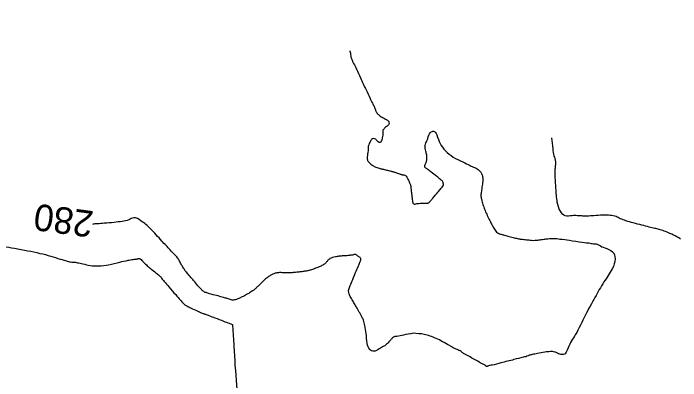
# Model space of a CAD drawing. Extents: x -478102 to -473059, y -1117705 to -1114104.
# Drawn here: x -474560.9 to -474460.1, y -1114300.7 to -1114245.3 of the extents above; entities that cross this region are included whole.
import ezdxf

# ---------------------------------------------------------------- set-up
doc = ezdxf.new("R2010")
doc.units = 0
for name, color, linetype in [('Vrstevnice_hlavni', 7, 'Continuous'), ('Vrstevnice_popis', 7, 'Continuous'), ('Vrstevnice_vedlejsi', 7, 'Continuous')]:
    doc.layers.add(name, color=color, linetype=linetype)

msp = doc.modelspace()

# ---------------------------------------------------------------- linework, layer by layer
at = {"layer": 'Vrstevnice_hlavni'}
for points in [[(-474510.104, -1114250.97), (-474510.091, -1114251.018), (-474510.014, -1114251.351), (-474509.96, -1114251.74), (-474509.859, -1114252.123), (-474509.71, -1114252.502), (-474509.513, -1114252.875), (-474509.103, -1114253.728), (-474508.479, -1114255.061), (-474507.64, -1114256.874), (-474507.041, -1114258.153), (-474506.68, -1114258.898), (-474506.557, -1114259.11), (-474506.422, -1114259.396), (-474506.273, -1114259.758)], [(-474506.273, -1114259.758), (-474506.111, -1114260.194), (-474505.763, -1114260.61), (-474505.229, -1114261.006), (-474504.508, -1114261.383), (-474504.179, -1114261.757), (-474504.243, -1114262.13), (-474504.7, -1114262.502), (-474504.996, -1114262.829), (-474505.131, -1114263.113), (-474505.106, -1114263.352), (-474505.131, -1114263.683), (-474505.208, -1114264.104), (-474505.337, -1114264.617), (-474505.543, -1114264.826), (-474505.826, -1114264.731), (-474506.188, -1114264.332), (-474506.515, -1114264.212), (-474506.807, -1114264.37), (-474507.065, -1114264.806), (-474507.234, -1114265.156), (-474507.313, -1114265.419), (-474507.303, -1114265.596), (-474507.322, -1114265.879), (-474507.37, -1114266.27), (-474507.447, -1114266.768), (-474507.472, -1114267.153), (-474507.445, -1114267.423), (-474507.367, -1114267.579), (-474507.232, -1114267.756), (-474507.04, -1114267.954), (-474506.791, -1114268.173), (-474506.538, -1114268.351), (-474506.281, -1114268.489), (-474506.019, -1114268.587), (-474505.642, -1114268.698), (-474505.148, -1114268.823), (-474504.538, -1114268.961), (-474503.987, -1114269.1), (-474503.496, -1114269.24), (-474503.063, -1114269.38), (-474502.726, -1114269.492), (-474502.482, -1114269.576), (-474502.333, -1114269.633), (-474502.17, -1114269.676), (-474501.991, -1114269.705), (-474501.797, -1114269.721), (-474501.592, -1114269.896), (-474501.375, -1114270.23), (-474501.147, -1114270.724), (-474500.992, -1114271.081), (-474500.91, -1114271.302), (-474500.9, -1114271.385), (-474500.867, -1114271.678), (-474500.811, -1114272.179), (-474500.732, -1114272.888), (-474500.665, -1114273.421), (-474500.611, -1114273.778), (-474500.569, -1114273.96), (-474500.449, -1114274.063), (-474500.25, -1114274.087), (-474499.973, -1114274.034), (-474499.649, -1114273.997), (-474499.277, -1114273.975), (-474498.859, -1114273.97), (-474498.548, -1114273.961), (-474498.344, -1114273.946), (-474498.248, -1114273.927), (-474498.127, -1114273.846), (-474497.98, -1114273.702), (-474497.808, -1114273.495), (-474497.51, -1114273.141), (-474497.084, -1114272.641), (-474496.532, -1114271.992), (-474496.161, -1114271.531), (-474495.97, -1114271.258), (-474495.959, -1114271.171), (-474495.97, -1114271.056), (-474496.002, -1114270.912), (-474496.054, -1114270.74), (-474496.379, -1114270.407), (-474496.976, -1114269.914), (-474497.844, -1114269.26), (-474498.433, -1114268.799), (-474498.743, -1114268.53), (-474498.773, -1114268.455), (-474498.745, -1114268.284), (-474498.658, -1114268.017), (-474498.512, -1114267.656), (-474498.456, -1114267.219), (-474498.49, -1114266.708), (-474498.615, -1114266.122), (-474498.698, -1114265.686), (-474498.74, -1114265.399), (-474498.741, -1114265.263), (-474498.601, -1114264.866), (-474498.32, -1114264.208)], [(-474498.32, -1114264.208), (-474497.898, -1114263.29), (-474497.45, -1114263.108), (-474496.974, -1114263.664), (-474496.471, -1114264.956), (-474495.643, -1114266.068), (-474494.49, -1114266.999), (-474493.012, -1114267.75), (-474491.938, -1114268.282), (-474491.268, -1114268.595), (-474491.003, -1114268.69), (-474490.736, -1114268.866), (-474490.468, -1114269.125), (-474490.199, -1114269.466), (-474490.054, -1114269.978), (-474490.035, -1114270.659), (-474490.141, -1114271.511), (-474490.224, -1114272.138), (-474490.283, -1114272.54), (-474490.318, -1114272.716), (-474490.272, -1114273.074), (-474490.145, -1114273.612), (-474489.937, -1114274.33), (-474489.669, -1114275.067), (-474489.341, -1114275.822), (-474488.953, -1114276.596), (-474488.629, -1114277.225), (-474488.369, -1114277.71), (-474488.171, -1114278.051), (-474487.936, -1114278.316), (-474487.664, -1114278.505), (-474487.355, -1114278.617), (-474486.879, -1114278.762), (-474486.236, -1114278.939), (-474485.427, -1114279.148), (-474484.756, -1114279.299), (-474484.222, -1114279.393), (-474483.825, -1114279.429), (-474483.433, -1114279.47), (-474483.048, -1114279.515), (-474482.668, -1114279.566), (-474482.171, -1114279.564), (-474481.556, -1114279.509), (-474480.824, -1114279.402), (-474480.202, -1114279.327), (-474479.69, -1114279.286), (-474479.289, -1114279.279), (-474478.373, -1114279.368), (-474476.943, -1114279.555), (-474474.999, -1114279.839), (-474473.676, -1114280.026), (-474472.974, -1114280.117), (-474472.894, -1114280.112), (-474472.442, -1114280.304), (-474471.618, -1114280.694), (-474470.422, -1114281.281), (-474470.043, -1114282.336), (-474470.481, -1114283.859), (-474471.737, -1114285.851), (-474473.084, -1114288.173), (-474474.521, -1114290.825), (-474476.049, -1114293.806), (-474477.152, -1114295.796), (-474477.829, -1114296.793), (-474478.08, -1114296.798), (-474478.387, -1114296.737), (-474478.749, -1114296.609), (-474479.166, -1114296.415), (-474479.808, -1114296.354), (-474480.673, -1114296.425), (-474481.762, -1114296.63), (-474482.541, -1114296.791), (-474483.009, -1114296.91), (-474483.167, -1114296.987), (-474483.934, -1114297.202), (-474485.309, -1114297.556), (-474487.293, -1114298.05), (-474488.628, -1114298.385), (-474489.313, -1114298.563), (-474489.347, -1114298.584), (-474489.387, -1114298.593), (-474489.431, -1114298.59), (-474489.479, -1114298.576), (-474489.521, -1114298.556), (-474489.556, -1114298.53), (-474489.585, -1114298.498), (-474489.993, -1114298.258), (-474490.78, -1114297.812), (-474491.946, -1114297.158), (-474492.73, -1114296.716), (-474493.13, -1114296.485), (-474493.147, -1114296.466), (-474493.81, -1114296.106), (-474495.121, -1114295.403), (-474497.078, -1114294.359), (-474498.879, -1114293.755), (-474500.524, -1114293.592)], [(-474536.346, -1114281.886), (-474536.522, -1114281.747), (-474537.225, -1114281.017), (-474538.455, -1114279.698), (-474540.213, -1114277.789), (-474541.632, -1114276.615), (-474542.713, -1114276.176), (-474543.454, -1114276.472), (-474544.442, -1114276.706), (-474545.676, -1114276.879), (-474547.155, -1114276.99), (-474548.174, -1114277.072), (-474548.732, -1114277.124), (-474548.929, -1114277.17)], [(-474500.524, -1114293.592), (-474502.013, -1114293.868), (-474503.01, -1114294.055), (-474503.516, -1114294.153), (-474503.529, -1114294.162), (-474503.682, -1114294.326), (-474503.975, -1114294.644), (-474504.406, -1114295.117), (-474504.967, -1114295.552), (-474505.657, -1114295.949), (-474506.475, -1114296.307), (-474507.077, -1114296.035), (-474507.463, -1114295.132), (-474507.633, -1114293.597), (-474507.823, -1114292.418), (-474508.034, -1114291.594), (-474508.265, -1114291.126), (-474508.493, -1114290.687), (-474508.716, -1114290.276), (-474508.935, -1114289.893), (-474509.213, -1114289.417), (-474509.551, -1114288.848), (-474509.949, -1114288.187), (-474510.196, -1114287.657), (-474510.291, -1114287.259), (-474510.235, -1114286.993), (-474510.024, -1114286.396), (-474509.656, -1114285.469), (-474509.133, -1114284.211), (-474508.753, -1114283.305), (-474508.518, -1114282.751), (-474508.427, -1114282.548), (-474508.415, -1114282.375), (-474508.484, -1114282.232), (-474508.632, -1114282.119), (-474508.79, -1114282.002), (-474508.958, -1114281.881), (-474509.136, -1114281.756), (-474509.289, -1114281.694), (-474509.418, -1114281.694), (-474509.522, -1114281.758), (-474509.837, -1114281.816), (-474510.362, -1114281.868), (-474511.097, -1114281.914), (-474511.734, -1114281.978), (-474512.273, -1114282.059), (-474512.714, -1114282.158), (-474513.091, -1114282.331), (-474513.404, -1114282.579), (-474513.653, -1114282.901), (-474514.044, -1114283.211), (-474514.577, -1114283.507), (-474515.252, -1114283.789), (-474515.867, -1114284.006), (-474516.421, -1114284.157), (-474516.915, -1114284.242), (-474517.475, -1114284.319), (-474518.102, -1114284.388), (-474518.795, -1114284.448), (-474519.441, -1114284.476), (-474520.041, -1114284.471), (-474520.593, -1114284.434), (-474521.106, -1114284.48), (-474521.579, -1114284.61), (-474522.013, -1114284.824), (-474522.458, -1114285.117), (-474522.914, -1114285.488), (-474523.382, -1114285.938), (-474523.8, -1114286.336), (-474524.169, -1114286.682), (-474524.487, -1114286.976), (-474524.931, -1114287.298), (-474525.498, -1114287.646), (-474526.191, -1114288.021), (-474526.758, -1114288.298), (-474527.199, -1114288.476), (-474527.514, -1114288.555), (-474527.829, -1114288.568), (-474528.142, -1114288.513), (-474528.455, -1114288.392), (-474528.987, -1114288.228), (-474529.739, -1114288.019), (-474530.711, -1114287.766), (-474531.433, -1114287.563), (-474531.907, -1114287.41), (-474532.131, -1114287.308), (-474532.501, -1114286.979), (-474533.016, -1114286.424), (-474533.677, -1114285.643), (-474534.2, -1114285.027), (-474534.587, -1114284.578), (-474534.837, -1114284.294), (-474535.124, -1114283.884), (-474535.448, -1114283.348), (-474535.809, -1114282.687), (-474536.109, -1114282.199), (-474536.346, -1114281.886)]]:
    msp.add_spline(points, degree=3, dxfattribs=at)
at = {"layer": 'Vrstevnice_vedlejsi'}
for points in [[(-474552.854, -1114311.249), (-474553.079, -1114311.087), (-474553.821, -1114310.574), (-474555.08, -1114309.711), (-474556.857, -1114308.497), (-474559.696, -1114307.123), (-474563.598, -1114305.587), (-474568.562, -1114303.891), (-474573.331, -1114301.997), (-474577.905, -1114299.906), (-474582.284, -1114297.617), (-474585.674, -1114295.919), (-474588.077, -1114294.812), (-474589.491, -1114294.296), (-474591.989, -1114293.662), (-474595.57, -1114292.908), (-474600.235, -1114292.036), (-474603.58, -1114291.444), (-474605.605, -1114291.133), (-474606.31, -1114291.102), (-474606.928, -1114291.027), (-474607.46, -1114290.909), (-474607.905, -1114290.747), (-474608.453, -1114290.591), (-474609.102, -1114290.44), (-474609.854, -1114290.294), (-474613.621, -1114289.328), (-474620.404, -1114287.542), (-474630.202, -1114284.937), (-474637.239, -1114282.941), (-474641.515, -1114281.554), (-474643.03, -1114280.777), (-474646.226, -1114278.86), (-474651.102, -1114275.804), (-474657.658, -1114271.609), (-474662.169, -1114268.281), (-474664.633, -1114265.821), (-474665.051, -1114264.228), (-474666.944, -1114260.949), (-474670.313, -1114255.984), (-474675.156, -1114249.332), (-474681.278, -1114245.965), (-474688.679, -1114245.885), (-474697.358, -1114249.09), (-474704.556, -1114251.174), (-474710.273, -1114252.136), (-474714.508, -1114251.976), (-474720.156, -1114252.317), (-474727.217, -1114253.156), (-474735.691, -1114254.496), (-474743.099, -1114255.448), (-474749.443, -1114256.012), (-474754.721, -1114256.188), (-474759.428, -1114257.754), (-474763.562, -1114260.711), (-474767.123, -1114265.059), (-474771.341, -1114269.134), (-474776.214, -1114272.938), (-474781.743, -1114276.469), (-474786.123, -1114279.544), (-474789.352, -1114282.163), (-474791.432, -1114284.326), (-474793.539, -1114286.068), (-474795.674, -1114287.39), (-474797.837, -1114288.291), (-474801.021, -1114290.603), (-474805.227, -1114294.326), (-474810.453, -1114299.461), (-474815.93, -1114304.595), (-474821.656, -1114309.73), (-474827.632, -1114314.865), (-474832.327, -1114319.021), (-474835.739, -1114322.197), (-474837.87, -1114324.394), (-474841.8, -1114328.201), (-474847.532, -1114333.618), (-474855.063, -1114340.645), (-474860.556, -1114345.784), (-474864.01, -1114349.037), (-474865.424, -1114350.402), (-474866.85, -1114351.834), (-474868.286, -1114353.332), (-474869.734, -1114354.897), (-474871.228, -1114357.206), (-474872.768, -1114360.258), (-474874.355, -1114364.053), (-474875.677, -1114367.182), (-474876.734, -1114369.645), (-474877.527, -1114371.441), (-474878.751, -1114373.179), (-474880.405, -1114374.858), (-474882.489, -1114376.478), (-474884.757, -1114377.858), (-474887.208, -1114379), (-474889.844, -1114379.903), (-474893.032, -1114381.02), (-474896.771, -1114382.352)], [(-474620.341, -1114261.799), (-474618.559, -1114262.645), (-474617.158, -1114263.319), (-474616.138, -1114263.821), (-474615.498, -1114264.15), (-474614.425, -1114264.619), (-474612.918, -1114265.229), (-474610.977, -1114265.98), (-474609.537, -1114266.741), (-474608.6, -1114267.514), (-474608.165, -1114268.297), (-474607.008, -1114269.493), (-474605.13, -1114271.101), (-474602.53, -1114273.123), (-474600.61, -1114274.596), (-474599.369, -1114275.522), (-474598.808, -1114275.899), (-474598.164, -1114276.165), (-474597.435, -1114276.321), (-474596.623, -1114276.365), (-474595.719, -1114276.405), (-474594.722, -1114276.441), (-474593.634, -1114276.474), (-474592.211, -1114276.487), (-474590.452, -1114276.482), (-474588.358, -1114276.458), (-474586.824, -1114276.467), (-474585.851, -1114276.509), (-474585.439, -1114276.584), (-474584.626, -1114276.512), (-474583.414, -1114276.294), (-474581.803, -1114275.929), (-474580.635, -1114275.65), (-474579.911, -1114275.458), (-474579.631, -1114275.351), (-474579.116, -1114275.345), (-474578.366, -1114275.438), (-474577.382, -1114275.631), (-474576.639, -1114275.783), (-474576.138, -1114275.892), (-474575.878, -1114275.958), (-474575.186, -1114276.211), (-474574.064, -1114276.649), (-474572.511, -1114277.273), (-474570.896, -1114277.903), (-474569.219, -1114278.538), (-474567.479, -1114279.179), (-474565.99, -1114279.669), (-474564.75, -1114280.007), (-474563.76, -1114280.194), (-474562.421, -1114280.444), (-474560.735, -1114280.756), (-474558.7, -1114281.13), (-474556.865, -1114281.529), (-474555.23, -1114281.953), (-474553.795, -1114282.401), (-474552.741, -1114282.7), (-474552.068, -1114282.85), (-474551.775, -1114282.85), (-474551.216, -1114282.937), (-474550.39, -1114283.112), (-474549.296, -1114283.374), (-474548, -1114283.417), (-474546.501, -1114283.243), (-474544.799, -1114282.851), (-474543.57, -1114282.583), (-474542.814, -1114282.438), (-474542.531, -1114282.416), (-474542.295, -1114282.383), (-474542.106, -1114282.339), (-474541.964, -1114282.282), (-474541.757, -1114282.366), (-474541.486, -1114282.59), (-474541.15, -1114282.956), (-474540.684, -1114283.391), (-474540.089, -1114283.896), (-474539.364, -1114284.471), (-474538.858, -1114284.895), (-474538.572, -1114285.168), (-474538.506, -1114285.289), (-474538.118, -1114285.761), (-474537.408, -1114286.583), (-474536.377, -1114287.756), (-474535.649, -1114288.586), (-474535.225, -1114289.072), (-474535.103, -1114289.216), (-474534.714, -1114289.453), (-474534.056, -1114289.783), (-474533.129, -1114290.207), (-474532.46, -1114290.503), (-474532.048, -1114290.671), (-474531.893, -1114290.711), (-474531.359, -1114290.905), (-474530.447, -1114291.251), (-474529.157, -1114291.751), (-474528.294, -1114292.084), (-474527.857, -1114292.249)], [(-474460.148, -1114279.397), (-474460.742, -1114279.036), (-474461.76, -1114278.543), (-474462.649, -1114278.167), (-474463.41, -1114277.908), (-474464.042, -1114277.764), (-474464.903, -1114277.556), (-474465.993, -1114277.284), (-474467.312, -1114276.947), (-474468.401, -1114276.62), (-474469.26, -1114276.301), (-474469.89, -1114275.993), (-474470.768, -1114275.817), (-474471.894, -1114275.774), (-474473.268, -1114275.865), (-474474.282, -1114275.911), (-474474.936, -1114275.913), (-474475.23, -1114275.87), (-474475.765, -1114275.848), (-474476.541, -1114275.847), (-474477.559, -1114275.866), (-474478.303, -1114275.185), (-474478.774, -1114273.804), (-474478.97, -1114271.723), (-474479.077, -1114270.108), (-474479.092, -1114268.962), (-474479.017, -1114268.283), (-474479.014, -1114267.705), (-474479.083, -1114267.23), (-474479.224, -1114266.856), (-474479.406, -1114265.75), (-474479.607, -1114264.11)], [(-474553.927, -1114400.416), (-474553.474, -1114399.617), (-474552.966, -1114398.863), (-474552.405, -1114398.155), (-474551.791, -1114397.492), (-474551.19, -1114396.826), (-474550.604, -1114396.156), (-474550.032, -1114395.484), (-474549.553, -1114394.754), (-474549.166, -1114393.968), (-474548.873, -1114393.124), (-474548.652, -1114392.233), (-474548.504, -1114391.292), (-474548.43, -1114390.304), (-474548.405, -1114389.279), (-474548.431, -1114388.218), (-474548.507, -1114387.121), (-474548.593, -1114386.176), (-474548.689, -1114385.383), (-474548.794, -1114384.743), (-474548.782, -1114383.719), (-474548.652, -1114382.312), (-474548.405, -1114380.522), (-474548.2, -1114379.213), (-474548.037, -1114378.385), (-474547.916, -1114378.037), (-474547.76, -1114377.133), (-474547.57, -1114375.673), (-474547.346, -1114373.655), (-474547.183, -1114372.254), (-474547.08, -1114371.47), (-474547.037, -1114371.302), (-474546.918, -1114370.892), (-474546.722, -1114370.241), (-474546.45, -1114369.347), (-474546.291, -1114368.58), (-474546.246, -1114367.94), (-474546.315, -1114367.427), (-474546.69, -1114366.615), (-474547.372, -1114365.504), (-474548.361, -1114364.094), (-474549.165, -1114362.891), (-474549.784, -1114361.892), (-474550.219, -1114361.1), (-474550.631, -1114360.14), (-474551.023, -1114359.011), (-474551.392, -1114357.714), (-474551.776, -1114356.302), (-474552.174, -1114354.773), (-474552.587, -1114353.128), (-474553.135, -1114351.671), (-474553.82, -1114350.403), (-474554.641, -1114349.324), (-474555.693, -1114348.305), (-474556.975, -1114347.347), (-474558.487, -1114346.449), (-474561.199, -1114344.714), (-474565.11, -1114342.144), (-474570.22, -1114338.737), (-474576.368, -1114334.802), (-474583.554, -1114330.338), (-474591.777, -1114325.345), (-474597.359, -1114321.978), (-474600.299, -1114320.235), (-474600.598, -1114320.118), (-474604.058, -1114319.093), (-474610.677, -1114317.161), (-474620.458, -1114314.323), (-474627.106, -1114312.405), (-474630.623, -1114311.409), (-474631.008, -1114311.334), (-474632.222, -1114311.03), (-474634.263, -1114310.497), (-474637.131, -1114309.734), (-474641.559, -1114307.935), (-474647.546, -1114305.101), (-474655.092, -1114301.231), (-474662.055, -1114298.079), (-474668.436, -1114295.643), (-474674.233, -1114293.924), (-474681.303, -1114292.66), (-474689.646, -1114291.85), (-474699.263, -1114291.494), (-474706.909, -1114291.13), (-474712.586, -1114290.757), (-474716.293, -1114290.376), (-474720.106, -1114290.354), (-474724.026, -1114290.69), (-474728.052, -1114291.384), (-474733.838, -1114291.971), (-474741.385, -1114292.45), (-474750.693, -1114292.823), (-474758.358, -1114294.589), (-474764.38, -1114297.75), (-474768.76, -1114302.305), (-474774.664, -1114306.585), (-474782.093, -1114310.591)], [(-474527.857, -1114292.249), (-474527.848, -1114292.246), (-474527.838, -1114292.25), (-474527.829, -1114292.26), (-474527.82, -1114292.276), (-474527.816, -1114292.295), (-474527.817, -1114292.316), (-474527.823, -1114292.341), (-474527.825, -1114292.385), (-474527.822, -1114292.451), (-474527.814, -1114292.537), (-474527.607, -1114295.525), (-474527.2, -1114301.416), (-474526.594, -1114310.208), (-474526.296, -1114316.187), (-474526.307, -1114319.353), (-474526.626, -1114319.706), (-474527.024, -1114320.209), (-474527.499, -1114320.863), (-474528.052, -1114321.666), (-474528.67, -1114322.429), (-474529.352, -1114323.149), (-474530.099, -1114323.829), (-474530.787, -1114324.494), (-474531.415, -1114325.147), (-474531.984, -1114325.786), (-474532.506, -1114326.547), (-474532.982, -1114327.429), (-474533.413, -1114328.433), (-474533.774, -1114329.243), (-474534.068, -1114329.859), (-474534.292, -1114330.28), (-474534.413, -1114330.645), (-474534.429, -1114330.954), (-474534.341, -1114331.206), (-474534.298, -1114331.524), (-474534.302, -1114331.909), (-474534.351, -1114332.36), (-474534.247, -1114333.15), (-474533.988, -1114334.277), (-474533.576, -1114335.742), (-474533.274, -1114336.852), (-474533.082, -1114337.608), (-474533.001, -1114338.009), (-474532.866, -1114338.393), (-474532.677, -1114338.762), (-474532.433, -1114339.115), (-474532.199, -1114339.736), (-474531.972, -1114340.626), (-474531.755, -1114341.785), (-474531.476, -1114343.1), (-474531.137, -1114344.571), (-474530.738, -1114346.198), (-474530.478, -1114347.34), (-474530.36, -1114347.996), (-474530.381, -1114348.167), (-474530.531, -1114348.934), (-474530.808, -1114350.296), (-474531.213, -1114352.254), (-474531.49, -1114353.58), (-474531.639, -1114354.273), (-474531.661, -1114354.334), (-474531.745, -1114354.654), (-474531.893, -1114355.233), (-474532.105, -1114356.07), (-474531.899, -1114356.479), (-474531.276, -1114356.46), (-474530.235, -1114356.014), (-474529.391, -1114355.438), (-474528.744, -1114354.734), (-474528.293, -1114353.901), (-474527.742, -1114353.153), (-474527.091, -1114352.49), (-474526.34, -1114351.913), (-474525.809, -1114351.284), (-474525.496, -1114350.604), (-474525.402, -1114349.871), (-474525.301, -1114348.594), (-474525.194, -1114346.772), (-474525.079, -1114344.407), (-474525.015, -1114342.777), (-474525.003, -1114341.884), (-474525.043, -1114341.728), (-474524.774, -1114341.021), (-474524.197, -1114339.765), (-474523.31, -1114337.959), (-474522.587, -1114336.38), (-474522.026, -1114335.028), (-474521.627, -1114333.903), (-474521.338, -1114332.941), (-474521.158, -1114332.141), (-474521.088, -1114331.503), (-474520.723, -1114330.765), (-474520.065, -1114329.927), (-474519.113, -1114328.99), (-474518.334, -1114328.213), (-474517.728, -1114327.597)]]:
    msp.add_spline(points, degree=3, dxfattribs=at)

# ---------------------------------------------------------------- texts
at = {"layer": 'Vrstevnice_popis'}
msp.add_text(' 280 ', height=4, rotation=172.37167, dxfattribs=at).set_placement((-474547.156, -1114275.394))

doc.saveas('drawing.dxf')
